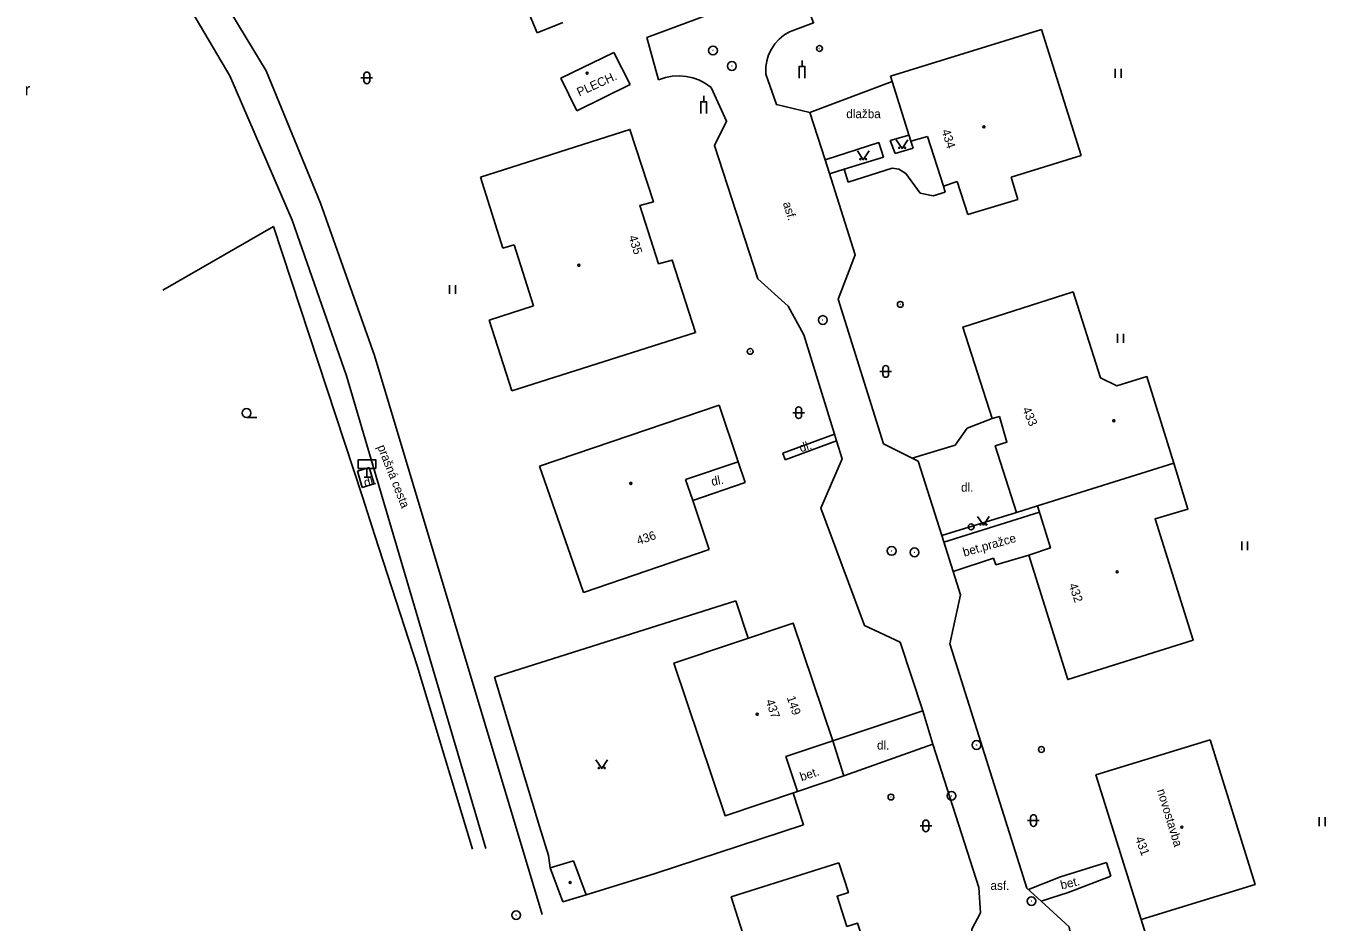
# Model space of a CAD drawing. Extents: x -544674 to -541478, y -1199076 to -1195527.
# Drawn here: x -542625.4 to -542514.1, y -1197843.4 to -1197766.6 of the extents above; entities that cross this region are included whole.
import ezdxf

# ---------------------------------------------------------------- set-up
doc = ezdxf.new("R2010")
doc.units = 0
for name, color, linetype in [('BUDOVY_MĚŘ', 7, 'Continuous'), ('BUDOVY_NEMĚŘ', 7, 'Continuous'), ('MAP_ZN_BP', 7, 'Continuous'), ('POMOC_POPIS', 7, 'Continuous'), ('ROZHRANÍ_PLOCH', 7, 'Continuous'), ('ZN_BP', 7, 'Continuous'), ('ZN_BUDOV', 7, 'Continuous'), ('ZN_DOPLŇKOVÉ', 7, 'Continuous'), ('ZN_KULTUR', 7, 'Continuous'), ('Č_POPIS_ORIENT', 7, 'Continuous')]:
    doc.layers.add(name, color=color, linetype=linetype)

msp = doc.modelspace()

# ---------------------------------------------------------------- linework, layer by layer
at = {"layer": 'BUDOVY_MĚŘ'}
for points in [[(-542583.56, -1197762.37), (-542581.58, -1197767.16)], [(-542581.58, -1197767.16), (-542579.38, -1197766.25)], [(-542575, -1197768.82), (-542579.53, -1197771.03)], [(-542573.6, -1197771.58), (-542575, -1197768.82)], [(-542579.53, -1197771.03), (-542578.17, -1197773.82)], [(-542578.17, -1197773.82), (-542573.6, -1197771.58)], [(-542551.3, -1197770.86), (-542549.54, -1197776.44)], [(-542586.44, -1197779.51), (-542573.62, -1197775.43), (-542571.61, -1197781.62), (-542572.77, -1197781.94), (-542571.17, -1197786.94), (-542570.01, -1197786.62), (-542568, -1197792.83), (-542583.75, -1197797.84)], [(-542538.69, -1197807.67), (-542540.5, -1197808.25), (-542542.31, -1197802.53), (-542541.31, -1197802.22), (-542541.95, -1197800.03), (-542542.57, -1197800.2), (-542545.08, -1197792.36), (-542535.64, -1197789.35), (-542533.29, -1197796.72), (-542531.9, -1197797.41), (-542529.32, -1197796.61), (-542527.01, -1197804.03)], [(-542581.37, -1197804.29), (-542565.98, -1197799.06)], [(-542565.98, -1197799.06), (-542564.34, -1197803.9)], [(-542564.34, -1197803.9), (-542568.86, -1197805.44)], [(-542538.69, -1197807.67), (-542527.01, -1197804.03), (-542525.8, -1197807.96), (-542528.61, -1197808.8), (-542525.36, -1197819.2), (-542536.1, -1197822.58), (-542539.44, -1197811.91), (-542537.58, -1197811.29), (-542538.69, -1197807.67)], [(-542577.61, -1197815.12), (-542581.37, -1197804.29)], [(-542568.86, -1197805.44), (-542568.24, -1197807.23)], [(-542568.24, -1197807.23), (-542566.82, -1197811.43)], [(-542566.82, -1197811.43), (-542577.61, -1197815.12)], [(-542569.85, -1197821.17), (-542559.62, -1197817.74), (-542556.24, -1197827.82), (-542560.25, -1197829.17), (-542559.25, -1197832.18), (-542565.46, -1197834.25), (-542569.85, -1197821.17)], [(-542523.88, -1197827.73), (-542533.68, -1197830.74), (-542529.82, -1197843.13), (-542520.05, -1197840.13), (-542523.88, -1197827.73)], [(-542579.36, -1197841.62), (-542580.45, -1197838.71)], [(-542555.73, -1197838.27), (-542564.93, -1197841.2), (-542560.96, -1197853.67), (-542551.75, -1197850.74), (-542554.11, -1197843.44), (-542555.02, -1197843.73), (-542555.86, -1197841.14), (-542554.9, -1197840.83), (-542555.73, -1197838.27)], [(-542577.37, -1197841.02), (-542579.36, -1197841.62)]]:
    msp.add_lwpolyline(points, dxfattribs=at)
at = {"layer": 'BUDOVY_NEMĚŘ'}
for points in [[(-542551.3, -1197770.86), (-542538.36, -1197766.87)], [(-542538.36, -1197766.87), (-542534.95, -1197777.65)], [(-542548.11, -1197776.04), (-542549.54, -1197776.44)], [(-542546.74, -1197780.3), (-542548.11, -1197776.04)], [(-542534.95, -1197777.65), (-542540.96, -1197779.53)], [(-542584.5, -1197785.61), (-542586.44, -1197779.51)], [(-542540.96, -1197779.53), (-542540.37, -1197781.44)], [(-542545.58, -1197779.9), (-542546.74, -1197780.3)], [(-542544.67, -1197782.73), (-542545.58, -1197779.9)], [(-542540.37, -1197781.44), (-542544.67, -1197782.73)], [(-542583.55, -1197785.31), (-542584.5, -1197785.61)], [(-542581.88, -1197790.55), (-542583.55, -1197785.31)], [(-542585.69, -1197791.76), (-542581.88, -1197790.55)], [(-542583.75, -1197797.84), (-542585.69, -1197791.76)], [(-542580.45, -1197838.71), (-542578.46, -1197838.11)], [(-542577.37, -1197841.02), (-542578.46, -1197838.11)]]:
    msp.add_lwpolyline(points, dxfattribs=at)
at = {"layer": 'MAP_ZN_BP'}
for centre, radius in [((-542566.5, -1197768.66), 0.375), ((-542566.5, -1197768.66), 0.0005), ((-542564.88, -1197769.991), 0.375), ((-542564.88, -1197769.991), 0.0005), ((-542557.09, -1197791.761), 0.375), ((-542557.09, -1197791.761), 0.0005), ((-542551.19, -1197811.551), 0.375), ((-542551.19, -1197811.551), 0.0005), ((-542549.23, -1197811.67), 0.375), ((-542549.23, -1197811.67), 0.0005), ((-542543.91, -1197828.181), 0.375), ((-542543.91, -1197828.181), 0.0005), ((-542546.06, -1197832.541), 0.375), ((-542546.06, -1197832.541), 0.0005), ((-542539.2, -1197841.561), 0.375), ((-542539.2, -1197841.561), 0.0005), ((-542583.37, -1197842.761), 0.375), ((-542583.37, -1197842.761), 0.0005)]:
    msp.add_circle(centre, radius, dxfattribs=at)
at = {"layer": 'ROZHRANÍ_PLOCH'}
for points in [[(-542616.83, -1197750.53), (-542604.8, -1197770.41)], [(-542607.92, -1197770.84), (-542618.8, -1197752.39)], [(-542571.18, -1197771.18), (-542572.17, -1197767.55), (-542559.23, -1197762.72), (-542557.88, -1197766.29), (-542559.95, -1197767.07)], [(-542559.95, -1197767.07), (-542560.42, -1197767.35), (-542560.84, -1197767.69), (-542561.2, -1197768.09), (-542561.5, -1197768.54), (-542561.74, -1197769.03), (-542561.89, -1197769.54), (-542561.97, -1197770.08), (-542561.97, -1197770.68)], [(-542604.8, -1197770.41), (-542600.15, -1197781.74)], [(-542561.97, -1197770.68), (-542561.06, -1197773.29), (-542558.19, -1197773.98)], [(-542602.58, -1197783.2), (-542607.92, -1197770.84)], [(-542566.66, -1197771.83), (-542567.15, -1197771.49), (-542567.67, -1197771.21), (-542568.23, -1197771.01), (-542568.81, -1197770.88), (-542569.4, -1197770.83), (-542570, -1197770.87), (-542570.58, -1197770.98), (-542571.18, -1197771.18)], [(-542556.09, -1197801.53), (-542558.73, -1197793.03), (-542560.05, -1197790.57), (-542562.65, -1197788.24), (-542566.36, -1197776.8), (-542565.34, -1197774.72), (-542566.66, -1197771.83)], [(-542558.19, -1197773.98), (-542551.15, -1197771.32)], [(-542558.19, -1197773.98), (-542556.9, -1197778.04)], [(-542549.71, -1197775.91), (-542551.31, -1197776.38)], [(-542551.31, -1197776.38), (-542550.88, -1197777.49)], [(-542556.9, -1197778.04), (-542552.3, -1197776.55), (-542551.9, -1197777.79), (-542555.25, -1197778.82), (-542556.52, -1197779.23)], [(-542550.88, -1197777.49), (-542549.36, -1197777.03)], [(-542549.36, -1197777.03), (-542549.54, -1197776.44)], [(-542556.9, -1197778.04), (-542554.32, -1197786.16), (-542555.78, -1197789.97), (-542551.89, -1197802.37), (-542549.42, -1197803.6)], [(-542555.25, -1197778.82), (-542554.93, -1197779.95)], [(-542551.14, -1197778.75), (-542554.93, -1197779.95)], [(-542550.57, -1197778.83), (-542551.14, -1197778.75)], [(-542549.97, -1197779.19), (-542550.57, -1197778.83)], [(-542548.75, -1197780.89), (-542549.97, -1197779.19)], [(-542546.61, -1197780.8), (-542547.63, -1197781.12)], [(-542546.74, -1197780.3), (-542546.61, -1197780.8)], [(-542600.15, -1197781.74), (-542595.5, -1197794.81)], [(-542547.63, -1197781.12), (-542548.75, -1197780.89)], [(-542597.9, -1197796.55), (-542602.58, -1197783.2)], [(-542595.5, -1197794.81), (-542581.13, -1197842.7)], [(-542585.97, -1197837.06), (-542597.9, -1197796.55)], [(-542544.71, -1197801.03), (-542542.57, -1197800.2)], [(-542556.09, -1197801.53), (-542560.53, -1197803.16)], [(-542555.92, -1197802.1), (-542556.09, -1197801.53)], [(-542545.75, -1197802.49), (-542544.71, -1197801.03)], [(-542560.32, -1197803.73), (-542555.92, -1197802.1)], [(-542550.46, -1197819.37), (-542553.52, -1197817.95), (-542557.25, -1197807.87), (-542555.43, -1197803.67), (-542555.92, -1197802.1)], [(-542549.42, -1197803.6), (-542545.75, -1197802.49)], [(-542563.73, -1197805.69), (-542564.34, -1197803.9)], [(-542560.53, -1197803.16), (-542560.32, -1197803.73)], [(-542549.42, -1197803.6), (-542548.91, -1197803.86), (-542546.9, -1197810.22)], [(-542596.96, -1197804.72), (-542595.96, -1197804.4)], [(-542596.56, -1197806.1), (-542596.96, -1197804.72)], [(-542595.96, -1197804.4), (-542595.55, -1197805.81)], [(-542595.55, -1197805.81), (-542596.56, -1197806.1)], [(-542568.24, -1197807.23), (-542563.73, -1197805.69)], [(-542546.9, -1197810.22), (-542540.5, -1197808.25)], [(-542538.52, -1197808.22), (-542546.72, -1197810.81)], [(-542546.9, -1197810.22), (-542545.3, -1197815.3), (-542546.21, -1197819.52), (-542539.61, -1197840.44), (-542538.39, -1197841.56)], [(-542542.27, -1197812.73), (-542539.44, -1197811.91)], [(-542545.93, -1197813.31), (-542542.46, -1197812.17)], [(-542542.46, -1197812.17), (-542542.27, -1197812.73)], [(-542548.51, -1197825.25), (-542550.46, -1197819.37)], [(-542556.24, -1197827.82), (-542548.51, -1197825.25)], [(-542547.66, -1197828.12), (-542548.51, -1197825.25)], [(-542556.24, -1197827.82), (-542555.3, -1197830.83)], [(-542547.66, -1197828.12), (-542555.3, -1197830.83)], [(-542537.75, -1197867.49), (-542536.89, -1197863.37), (-542538.32, -1197859.49), (-542541.29, -1197856.38), (-542544.48, -1197845.8), (-542544.31, -1197843.96), (-542543.59, -1197842.57), (-542543.72, -1197840.39), (-542547.66, -1197828.12)], [(-542555.3, -1197830.83), (-542559.25, -1197832.18)], [(-542536.73, -1197839.49), (-542532.78, -1197838.25)], [(-542532.78, -1197838.25), (-542532.41, -1197839.41)], [(-542539.47, -1197840.57), (-542536.73, -1197839.49)], [(-542532.41, -1197839.41), (-542536.05, -1197840.81)], [(-542536.05, -1197840.81), (-542538.39, -1197841.56)], [(-542538.39, -1197841.56), (-542535.98, -1197843.77), (-542534.62, -1197852.37)]]:
    msp.add_lwpolyline(points, dxfattribs=at)
at = {"layer": 'ZN_BP'}
for centre, radius in [((-542557.38, -1197768.49), 0.25), ((-542557.38, -1197768.49), 0.0005), ((-542550.45, -1197790.42), 0.25), ((-542550.45, -1197790.42), 0.0005), ((-542563.31, -1197794.45), 0.25), ((-542563.31, -1197794.45), 0.0005), ((-542544.38, -1197809.48), 0.25), ((-542544.38, -1197809.48), 0.0005), ((-542538.36, -1197828.56), 0.25), ((-542538.36, -1197828.56), 0.0005), ((-542551.25, -1197832.64), 0.25), ((-542551.25, -1197832.64), 0.0005)]:
    msp.add_circle(centre, radius, dxfattribs=at)
at = {"layer": 'ZN_BUDOV'}
for centre in [(-542577.29, -1197770.61), (-542543.28, -1197775.21), (-542578, -1197787.07), (-542532.15, -1197800.39), (-542573.54, -1197805.76), (-542531.87, -1197813.35), (-542562.71, -1197825.55), (-542526.33, -1197835.22), (-542578.75, -1197839.96)]:
    msp.add_circle(centre, 0.0875, dxfattribs=at)
at = {"layer": 'ZN_DOPLŇKOVÉ'}
for p, q in [((-542558.87, -1197770.03), (-542558.87, -1197769.53)), ((-542567.3, -1197773.05), (-542567.3, -1197772.55)), ((-542596.41, -1197805.23), (-542595.91, -1197805.23)), ((-542596.16, -1197804.48), (-542596.16, -1197805.23))]:
    msp.add_line(p, q, dxfattribs=at)
for points in [[(-542559.12, -1197771.03), (-542559.12, -1197770.03), (-542558.62, -1197770.03), (-542558.62, -1197771.03)], [(-542567.55, -1197774.05), (-542567.55, -1197773.05), (-542567.05, -1197773.05), (-542567.05, -1197774.05)], [(-542604.17, -1197783.75), (-542613.65, -1197789.19)], [(-542596.54, -1197806.92), (-542604.17, -1197783.75)], [(-542595.48, -1197810.22), (-542596.54, -1197806.92)], [(-542591.86, -1197821.41), (-542595.48, -1197810.22)], [(-542564.54, -1197815.84), (-542585.24, -1197822.38)], [(-542563.48, -1197819.03), (-542564.54, -1197815.84)], [(-542587.12, -1197837.1), (-542591.86, -1197821.41)], [(-542585.24, -1197822.38), (-542581.38, -1197835.17)], [(-542558.75, -1197835.03), (-542559.63, -1197832.31)], [(-542580.6, -1197837.65), (-542581.38, -1197835.17)], [(-542571.45, -1197839.19), (-542558.75, -1197835.03)], [(-542580.6, -1197837.65), (-542580.45, -1197838.71)], [(-542577.37, -1197841.02), (-542571.45, -1197839.19)], [(-542529.82, -1197843.13), (-542528.79, -1197846.45)]]:
    msp.add_lwpolyline(points, dxfattribs=at)
msp.add_lwpolyline([(-542596.91, -1197804.48), (-542595.41, -1197804.48), (-542595.41, -1197803.73), (-542596.91, -1197803.73)], close=True, dxfattribs=at)
at = {"layer": 'ZN_KULTUR'}
for p, q in [((-542596.42, -1197771.26), (-542596.42, -1197770.76)), ((-542595.92, -1197771.26), (-542595.92, -1197770.76)), ((-542532.03, -1197770.995), (-542532.03, -1197770.245)), ((-542531.53, -1197770.995), (-542531.53, -1197770.245)), ((-542596.67, -1197771.01), (-542595.67, -1197771.01)), ((-542589.08, -1197789.515), (-542589.08, -1197788.765)), ((-542588.58, -1197789.515), (-542588.58, -1197788.765)), ((-542531.83, -1197793.705), (-542531.83, -1197792.955)), ((-542531.33, -1197793.705), (-542531.33, -1197792.955)), ((-542552.2, -1197796.17), (-542551.2, -1197796.17)), ((-542551.95, -1197796.42), (-542551.95, -1197795.92)), ((-542551.45, -1197796.42), (-542551.45, -1197795.92)), ((-542559.66, -1197799.7), (-542558.66, -1197799.7)), ((-542559.41, -1197799.95), (-542559.41, -1197799.45)), ((-542558.91, -1197799.95), (-542558.91, -1197799.45)), ((-542606.47, -1197800.105), (-542605.595, -1197800.105)), ((-542521.19, -1197811.495), (-542521.19, -1197810.745)), ((-542520.69, -1197811.495), (-542520.69, -1197810.745)), ((-542548.76, -1197835.11), (-542547.76, -1197835.11)), ((-542548.51, -1197835.36), (-542548.51, -1197834.86)), ((-542548.01, -1197835.36), (-542548.01, -1197834.86)), ((-542539.54, -1197834.66), (-542538.54, -1197834.66)), ((-542539.29, -1197834.91), (-542539.29, -1197834.41)), ((-542538.79, -1197834.91), (-542538.79, -1197834.41)), ((-542514.55, -1197835.125), (-542514.55, -1197834.375)), ((-542514.05, -1197835.125), (-542514.05, -1197834.375))]:
    msp.add_line(p, q, dxfattribs=at)
for points in [[(-542550.8, -1197776.31), (-542550.3, -1197777.06), (-542549.8, -1197776.31)], [(-542554.13, -1197777.27), (-542553.63, -1197778.02), (-542553.13, -1197777.27)], [(-542543.82, -1197808.59), (-542543.32, -1197809.34), (-542542.82, -1197808.59)], [(-542576.53, -1197829.45), (-542576.03, -1197830.2), (-542575.53, -1197829.45)]]:
    msp.add_lwpolyline(points, dxfattribs=at)
for centre, radius in [((-542550.55, -1197777.01), 0.05), ((-542550.05, -1197777.01), 0.05), ((-542553.88, -1197777.97), 0.05), ((-542553.38, -1197777.97), 0.05), ((-542606.47, -1197799.73), 0.375), ((-542543.57, -1197809.29), 0.05), ((-542543.07, -1197809.29), 0.05), ((-542576.28, -1197830.15), 0.05), ((-542575.78, -1197830.15), 0.05)]:
    msp.add_circle(centre, radius, dxfattribs=at)
for centre, start, end in [((-542596.17, -1197770.76), 0, 179.99999), ((-542596.17, -1197771.26), 179.99999, 359.99999), ((-542551.7, -1197795.92), 0, 179.99999), ((-542551.7, -1197796.42), 179.99999, 359.99999), ((-542559.16, -1197799.45), 0, 179.99999), ((-542559.16, -1197799.95), 179.99999, 359.99999), ((-542539.04, -1197834.41), 0, 179.99999), ((-542548.26, -1197834.86), 0, 179.99999), ((-542548.26, -1197835.36), 179.99999, 359.99999), ((-542539.04, -1197834.91), 179.99999, 359.99999)]:
    msp.add_arc(centre, 0.25, start, end, dxfattribs=at)

# ---------------------------------------------------------------- texts
at = {"layer": 'POMOC_POPIS'}
for s, rotation, p in [('PLECH.', 24.33999, (-542577.96, -1197772.61)), ('asf.', 287.41998, (-542560.52, -1197781.75)), ('prašná cesta', 291.59002, (-542595.28, -1197802.62)), ('dl.', 17.69001, (-542558.97, -1197803.1)), ('dl.', 14.86997, (-542596.32, -1197806.08)), ('dl.', 11.09, (-542566.58, -1197805.98)), ('bet.pražce', 15.87998, (-542544.97, -1197812.04)), ('bet.', 18.54, (-542558.91, -1197831.29)), ('novostavba', 287.07002, (-542528.46, -1197832.07)), ('bet.', 13.41002, (-542536.63, -1197840.56))]:
    msp.add_text(s, height=0.75, rotation=rotation, dxfattribs=at).set_placement(p)
for s, p in [('dlažba', (-542555.08, -1197774.46)), ('dl.', (-542545.24, -1197806.47)), ('dl.', (-542552.45, -1197828.57)), ('asf.', (-542542.72, -1197840.6))]:
    msp.add_text(s, height=0.75, dxfattribs=at).set_placement(p)
at = {"layer": 'ZN_KULTUR'}
msp.add_text('r', height=1, dxfattribs=at).set_placement((-542625.468, -1197772.492))
at = {"layer": 'Č_POPIS_ORIENT'}
for s, rotation, p in [('434', 287.73998, (-542546.92, -1197775.54)), ('435', 287.73998, (-542573.75, -1197784.62)), ('433', 293.17998, (-542540.01, -1197799.4)), ('436', 18.87999, (-542572.9, -1197811.05)), ('432', 289.19999, (-542536.03, -1197814.46)), ('149', 288.54, (-542560.19, -1197824.11)), ('437', 289.38998, (-542562, -1197824.41)), ('431', 290.79, (-542530.34, -1197836.18))]:
    msp.add_text(s, height=0.75, rotation=rotation, dxfattribs=at).set_placement(p)

doc.saveas('drawing.dxf')
